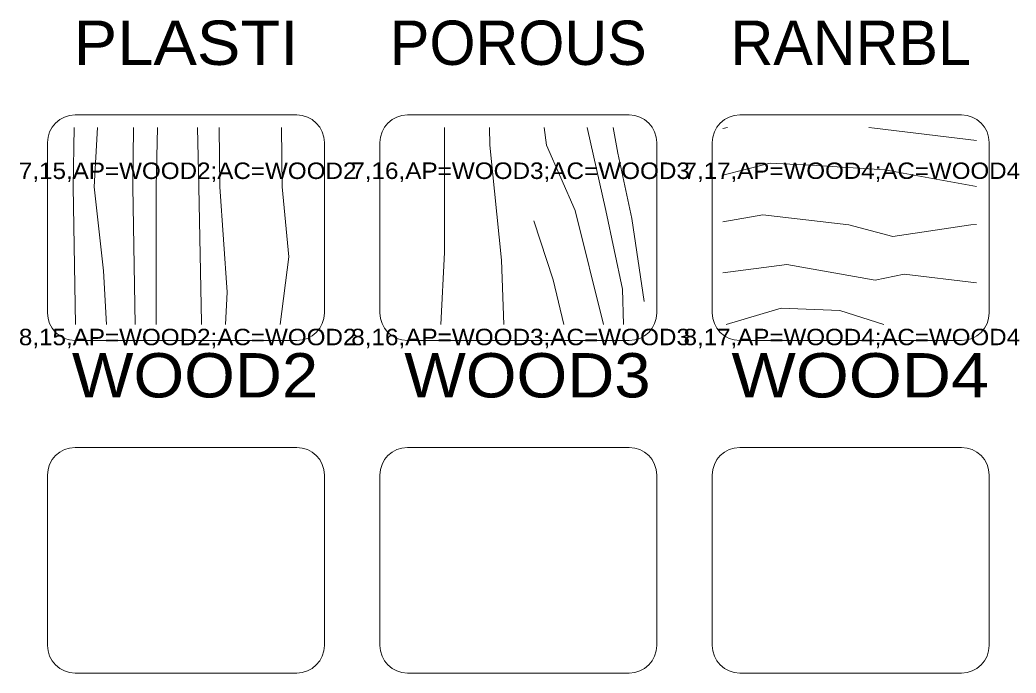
# Model space of a CAD drawing. Extents: x 95935 to 95946.4, y 95971.2 to 95974.7.
# Drawn here: x 95943.436 to 95945.234, y 95971.925 to 95973.103 of the extents above; entities that cross this region are included whole.
import ezdxf
from ezdxf.enums import TextEntityAlignment as Align

# ---------------------------------------------------------------- set-up
doc = ezdxf.new("R2010")
doc.units = 0
doc.header["$LTSCALE"] = 0.013
for name, color, linetype, lineweight in [('1', 7, 'Continuous', 13), ('6', 7, 'Continuous', 13), ('63', 7, 'Continuous', 13)]:
    doc.layers.add(name, color=color, linetype=linetype, lineweight=lineweight)
doc.layers.add('20', color=7, linetype='Continuous')

msp = doc.modelspace()

# ---------------------------------------------------------------- linework, layer by layer
at = {"layer": '1'}
for p, q in [((95943.5357, 95972.9318), (95943.9357, 95972.9318)), ((95944.1357, 95972.9318), (95944.5357, 95972.9318)), ((95944.7357, 95972.9318), (95945.1357, 95972.9318)), ((95943.4857, 95972.5747), (95943.4857, 95972.8818)), ((95943.9857, 95972.8818), (95943.9857, 95972.5747)), ((95944.0857, 95972.5747), (95944.0857, 95972.8818)), ((95944.5857, 95972.8818), (95944.5857, 95972.5747)), ((95944.6857, 95972.5747), (95944.6857, 95972.8818)), ((95945.1857, 95972.8818), (95945.1857, 95972.5747)), ((95943.9357, 95972.5247), (95943.5357, 95972.5247)), ((95944.5357, 95972.5247), (95944.1357, 95972.5247)), ((95945.1357, 95972.5247), (95944.7357, 95972.5247)), ((95943.5357, 95972.3318), (95943.9357, 95972.3318)), ((95944.1357, 95972.3318), (95944.5357, 95972.3318)), ((95944.7357, 95972.3318), (95945.1357, 95972.3318)), ((95944.7357, 95972.3318), (95945.1357, 95972.3318)), ((95943.4857, 95971.9747), (95943.4857, 95972.2818)), ((95943.9857, 95972.2818), (95943.9857, 95971.9747)), ((95944.0857, 95971.9747), (95944.0857, 95972.2818)), ((95944.5857, 95972.2818), (95944.5857, 95971.9747)), ((95944.6857, 95971.9747), (95944.6857, 95972.2818)), ((95944.6857, 95971.9747), (95944.6857, 95972.2818)), ((95945.1857, 95972.2818), (95945.1857, 95971.9747)), ((95945.1857, 95972.2818), (95945.1857, 95971.9747)), ((95943.9357, 95971.9247), (95943.5357, 95971.9247)), ((95944.5357, 95971.9247), (95944.1357, 95971.9247)), ((95945.1357, 95971.9247), (95944.7357, 95971.9247)), ((95945.1357, 95971.9247), (95944.7357, 95971.9247))]:
    msp.add_line(p, q, dxfattribs=at)
for centre, start, end in [((95943.5357, 95972.8818), 90, 180), ((95943.9357, 95972.8818), 0, 90), ((95944.1357, 95972.8818), 90, 180), ((95944.5357, 95972.8818), 0, 90), ((95944.7357, 95972.8818), 90, 180), ((95945.1357, 95972.8818), 0, 90), ((95943.5357, 95972.5747), 180, 270), ((95943.9357, 95972.5747), 270, 0), ((95944.1357, 95972.5747), 180, 270), ((95944.5357, 95972.5747), 270, 0), ((95944.7357, 95972.5747), 180, 270), ((95945.1357, 95972.5747), 270, 0), ((95943.5357, 95972.2818), 90, 180), ((95943.9357, 95972.2818), 0, 90), ((95944.1357, 95972.2818), 90, 180), ((95944.5357, 95972.2818), 0, 90), ((95944.7357, 95972.2818), 90, 180), ((95944.7357, 95972.2818), 90, 180), ((95945.1357, 95972.2818), 0, 90), ((95945.1357, 95972.2818), 0, 90), ((95943.5357, 95971.9747), 180, 270), ((95943.9357, 95971.9747), 270, 0), ((95944.1357, 95971.9747), 180, 270), ((95944.5357, 95971.9747), 270, 0), ((95944.7357, 95971.9747), 180, 270), ((95944.7357, 95971.9747), 180, 270), ((95945.1357, 95971.9747), 270, 0), ((95945.1357, 95971.9747), 270, 0)]:
    msp.add_arc(centre, 0.05, start, end, dxfattribs=at)
at = {"layer": '6'}
for p, q in [((95943.532, 95972.8022), (95943.534, 95972.9094)), ((95943.57, 95972.8022), (95943.5762, 95972.9094)), ((95943.6398, 95972.8022), (95943.6411, 95972.9094)), ((95943.6817, 95972.8022), (95943.6842, 95972.9094)), ((95943.7587, 95972.8022), (95943.7563, 95972.9094)), ((95943.7968, 95972.8022), (95943.7958, 95972.9094)), ((95943.9093, 95972.8022), (95943.9083, 95972.9094)), ((95944.7046, 95972.9072), (95944.7133, 95972.9094)), ((95943.5364, 95972.5536), (95943.532, 95972.8022)), ((95943.6438, 95972.5536), (95943.6398, 95972.8022)), ((95943.6817, 95972.5536), (95943.6817, 95972.8022))]:
    msp.add_line(p, q, dxfattribs=at)
for points in [[(95944.1958, 95972.5536), (95944.2026, 95972.6836), (95944.2026, 95972.9094)], [(95944.3096, 95972.5536), (95944.3056, 95972.6695), (95944.2842, 95972.8771), (95944.2835, 95972.9094)], [(95944.4896, 95972.5536), (95944.4381, 95972.7591), (95944.3868, 95972.8771), (95944.3824, 95972.9094)], [(95944.5258, 95972.5536), (95944.5236, 95972.6176), (95944.4937, 95972.7591), (95944.4597, 95972.9094)], [(95944.5628, 95972.5949), (95944.5407, 95972.745), (95944.5151, 95972.8629), (95944.507, 95972.9094)], [(95944.9686, 95972.9094), (95944.9787, 95972.9078), (95945.1628, 95972.8858)], [(95944.7046, 95972.823), (95944.7904, 95972.845), (95944.8731, 95972.8404), (95944.9974, 95972.8326), (95945.1628, 95972.8029)], [(95943.5922, 95972.5536), (95943.5871, 95972.6503), (95943.57, 95972.8022)], [(95943.7638, 95972.5536), (95943.764, 95972.5571), (95943.7587, 95972.8022)], [(95943.8071, 95972.5536), (95943.8101, 95972.6122), (95943.7968, 95972.8022)], [(95943.906, 95972.5536), (95943.9214, 95972.6758), (95943.9093, 95972.8022)], [(95944.418, 95972.5536), (95944.3987, 95972.6343), (95944.3637, 95972.7406)], [(95944.7046, 95972.7387), (95944.7772, 95972.7518), (95944.9321, 95972.7337), (95945.012, 95972.7123), (95945.1523, 95972.7337), (95945.1628, 95972.7339)], [(95944.7046, 95972.6469), (95944.8202, 95972.662), (95944.9799, 95972.6334), (95945.0323, 95972.6442), (95945.1628, 95972.6288)], [(95944.9957, 95972.5536), (95944.9163, 95972.579), (95944.8104, 95972.5829), (95944.7112, 95972.5536)]]:
    msp.add_lwpolyline(points, dxfattribs=at)

# ---------------------------------------------------------------- texts
at = {"layer": '20'}
for s, width, p in [('PLASTI', 1.1, (95943.7358, 95973.022)), (' WOOD2', 1.1, (95943.7358, 95972.422)), (' WOOD3', 1.1, (95944.3358, 95972.422)), (' WOOD4', 1.15, (95944.9358, 95972.422))]:
    msp.add_text(s, height=0.08, dxfattribs=dict(at, width=width)).set_placement(p, align=Align.CENTER)
for s, p in [('POROUS', (95944.3357, 95973.022)), ('RANRBL', (95944.9358, 95973.022))]:
    msp.add_text(s, height=0.08, dxfattribs=at).set_placement(p, align=Align.CENTER)
at = {"layer": '63', "width": 1.1}
for s, height, p in [('7,15,AP=WOOD2;AC=WOOD2', 0.0297, (95943.4341, 95972.8162)), ('7,16,AP=WOOD3;AC=WOOD3', 0.0298, (95944.0341, 95972.8162)), ('7,17,AP=WOOD4;AC=WOOD4', 0.0296, (95944.6341, 95972.8163)), ('8,15,AP=WOOD2;AC=WOOD2', 0.0297, (95943.4341, 95972.5162)), ('8,16,AP=WOOD3;AC=WOOD3', 0.0298, (95944.0341, 95972.5162)), ('8,17,AP=WOOD4;AC=WOOD4', 0.0296, (95944.6341, 95972.5163))]:
    msp.add_text(s, height=height, dxfattribs=at).set_placement(p)

doc.saveas('drawing.dxf')
